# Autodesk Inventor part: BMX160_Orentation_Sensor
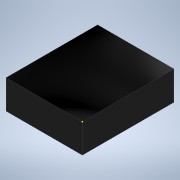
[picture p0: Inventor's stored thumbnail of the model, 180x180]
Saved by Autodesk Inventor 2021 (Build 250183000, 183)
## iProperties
Created: 2021-02
Part Number: BMX160_Orentation_Sensor
Material: Generic
Document SubType Name: Modeling
Designer: callu
Density: 1 g/cm^3
Appearance: Default
Author: callu
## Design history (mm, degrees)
sketch "Sketch1"
  geometry: L1 (0, 0)-(2.5, 0); L2 (2.5, 0)-(2.5, -3); L3 (2.5, -3)-(0, -3); L4 (0, -3)-(0, 0)
  constraints: 8 end point, 2 parallel, 1 horizontal, 1 perpendicular
  dimensions: "d0" = 2.5 distance of L2.end L3.end; "d1" = 3 distance of L1.end L2.end
extrude "Extrusion1" new body sketch "Sketch1" distance "d2" = 0.95; taper "d3" = 0 deg
sketch "Sketch2"
  geometry: 1 further point
body "Solid1"
